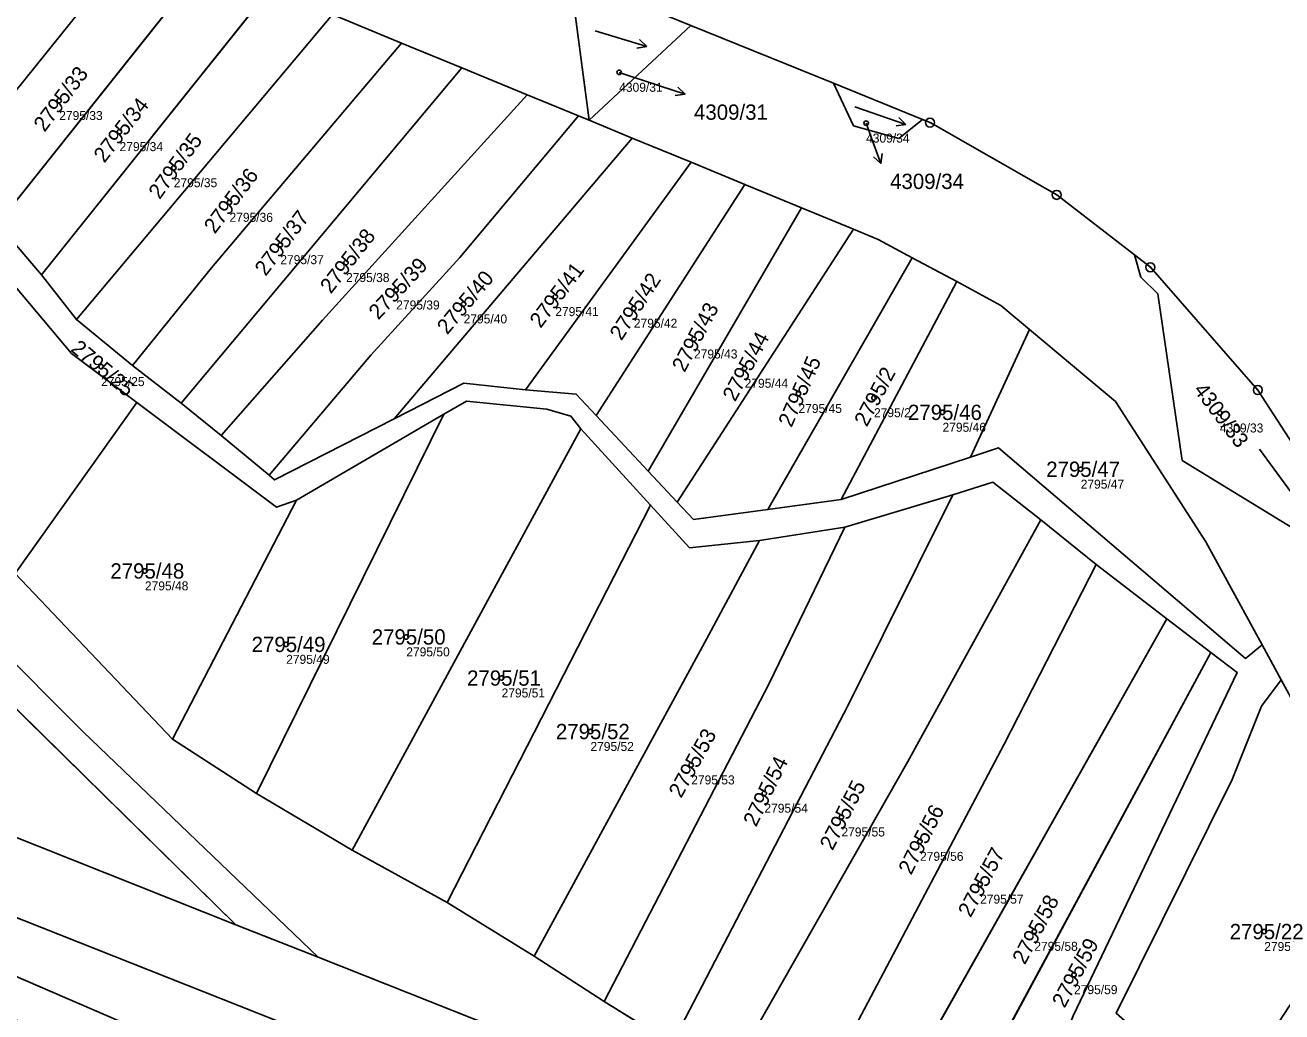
# Model space of a CAD drawing. Extents: x -739214 to -733252, y -1147612 to -1142842.
# Drawn here: x -737498.6 to -737358.8, y -1144401.4 to -1144291.6 of the extents above; entities that cross this region are included whole.
import ezdxf

# ---------------------------------------------------------------- set-up
doc = ezdxf.new("R2010")
doc.units = 0
for name, color, linetype in [('Definiční body', 7, 'Continuous'), ('Hranice parcel', 7, 'Continuous'), ('Parcelní čísla', 7, 'Continuous'), ('Polygon ku', 7, 'Continuous'), ('Polygon parcely', 7, 'Continuous'), ('Pop  PČ popisy', 7, 'Continuous'), ('Značky bodu BP', 7, 'Continuous'), ('Značky kultur', 7, 'Continuous')]:
    doc.layers.add(name, color=color, linetype=linetype)

msp = doc.modelspace()

# ---------------------------------------------------------------- linework, layer by layer
at = {"layer": 'Definiční body'}
for centre in [(-737432.55, -1144296.9), (-737494.83, -1144300.04), (-737405.09, -1144302.55), (-737488.12, -1144303.5), (-737482.09, -1144307.51), (-737475.89, -1144311.36), (-737470.24, -1144316.07), (-737462.93, -1144318.06), (-737457.35, -1144321.11), (-737439.66, -1144321.85), (-737449.85, -1144322.66), (-737430.92, -1144323.14), (-737424.23, -1144326.56), (-737490.17, -1144329.63), (-737418.6, -1144329.82), (-737412.61, -1144332.62), (-737404.21, -1144333.09), (-737396.59, -1144334.71), (-737365.74, -1144334.79), (-737381.22, -1144341.04), (-737485.3, -1144352.35), (-737456.23, -1144359.69), (-737469.59, -1144360.52), (-737445.63, -1144364.26), (-737435.75, -1144370.21), (-737424.54, -1144373.93), (-737416.4, -1144377.08), (-737407.83, -1144379.72), (-737399.09, -1144382.43), (-737392.41, -1144387.19), (-737386.38, -1144392.44), (-737360.81, -1144392.46), (-737381.96, -1144397.26)]:
    msp.add_circle(centre, 0.25, dxfattribs=at)
at = {"layer": 'Hranice parcel'}
for p, q in [((-737502.07, -1144314.24), (-737478.52, -1144284.68)), ((-737582.77, -1144286.02), (-737475.17, -1144391.69)), ((-737438.01, -1144286.21), (-737435.9, -1144302.23)), ((-737424.58, -1144291.67), (-737438.01, -1144286.21)), ((-737496.81, -1144319.43), (-737471.37, -1144287.62)), ((-737492.92, -1144324.38), (-737464.42, -1144290.48)), ((-737456.75, -1144293.64), (-737464.42, -1144290.48)), ((-737435.9, -1144302.23), (-737424.58, -1144291.67)), ((-737408.73, -1144298.11), (-737424.58, -1144291.67)), ((-737450.05, -1144296.4), (-737456.75, -1144293.64)), ((-737481.25, -1144333.69), (-737450.05, -1144296.4)), ((-737442.78, -1144299.39), (-737450.05, -1144296.4)), ((-737398.82, -1144302.14), (-737408.73, -1144298.11)), ((-737437.08, -1144301.74), (-737442.78, -1144299.39)), ((-737435.9, -1144302.23), (-737437.08, -1144301.74)), ((-737431.11, -1144304.2), (-737435.9, -1144302.23)), ((-737397.98, -1144302.48), (-737398.82, -1144302.14)), ((-737383.89, -1144310.52), (-737397.98, -1144302.48)), ((-737457.59, -1144335.43), (-737431.11, -1144304.2)), ((-737424.55, -1144306.9), (-737431.11, -1144304.2)), ((-737442.97, -1144332.19), (-737424.55, -1144306.9)), ((-737418.57, -1144309.37), (-737424.55, -1144306.9)), ((-737435.11, -1144335.05), (-737418.57, -1144309.37)), ((-737412.29, -1144311.95), (-737418.57, -1144309.37)), ((-737375.25, -1144317.2), (-737383.89, -1144310.52)), ((-737429.32, -1144341.24), (-737412.29, -1144311.95)), ((-737406.48, -1144314.34), (-737412.29, -1144311.95)), ((-737426.1, -1144344.69), (-737406.48, -1144314.34)), ((-737399.97, -1144317.54), (-737416, -1144345.53)), ((-737394.99, -1144320.15), (-737399.97, -1144317.54)), ((-737373.47, -1144318.58), (-737375.25, -1144317.2)), ((-737492.92, -1144324.38), (-737496.81, -1144319.43)), ((-737407.88, -1144344.42), (-737394.99, -1144320.15)), ((-737486.67, -1144329.49), (-737492.92, -1144324.38)), ((-737393.49, -1144339.68), (-737386.93, -1144325.49)), ((-737481.25, -1144333.69), (-737486.67, -1144329.49)), ((-737499.72, -1144352.62), (-737486.18, -1144333.6)), ((-737476.83, -1144337.27), (-737481.25, -1144333.69)), ((-737472.9, -1144377.11), (-737452.04, -1144334.92)), ((-737468.45, -1144344.48), (-737452.04, -1144334.92)), ((-737429.32, -1144341.24), (-737435.11, -1144335.05)), ((-737471.49, -1144341.7), (-737476.83, -1144337.27)), ((-737462.26, -1144383.41), (-737436.81, -1144336.54)), ((-737436.81, -1144336.54), (-737429.06, -1144345.03)), ((-737393.49, -1144339.68), (-737407.88, -1144344.42)), ((-737426.1, -1144344.69), (-737429.32, -1144341.24)), ((-737407.46, -1144347.49), (-737395.43, -1144343.89)), ((-737482.25, -1144371.07), (-737468.45, -1144344.48)), ((-737451.67, -1144389.22), (-737429.06, -1144345.03)), ((-737416, -1144345.53), (-737407.88, -1144344.42)), ((-737385.64, -1144346.65), (-737379.51, -1144351.64)), ((-737416.94, -1144348.97), (-737407.46, -1144347.49)), ((-737482.25, -1144371.07), (-737499.72, -1144352.62)), ((-737379.51, -1144351.64), (-737371.64, -1144357.66)), ((-737405.79, -1144418.29), (-737371.64, -1144357.66)), ((-737371.64, -1144357.66), (-737366.74, -1144361.41)), ((-737358.92, -1144364.45), (-737361.05, -1144360.55)), ((-737399.28, -1144421.75), (-737366.74, -1144361.41)), ((-737472.9, -1144377.11), (-737482.25, -1144371.07)), ((-737462.26, -1144383.41), (-737472.9, -1144377.11)), ((-737451.67, -1144389.22), (-737462.26, -1144383.41)), ((-737442.02, -1144395.2), (-737451.67, -1144389.22)), ((-737466.04, -1144395.32), (-737475.17, -1144391.69)), ((-737434.22, -1144400.22), (-737442.02, -1144395.2)), ((-737426.67, -1144404.91), (-737434.22, -1144400.22))]:
    msp.add_line(p, q, dxfattribs=at)
for points in [[(-737509.32, -1144310.65), (-737501.23, -1144300.88), (-737485.8, -1144281.68)], [(-737466.04, -1144395.32), (-737492.16, -1144370.24), (-737532.88, -1144329.44), (-737578.49, -1144285.03)], [(-737486.67, -1144329.49), (-737477.89, -1144318.64), (-737456.75, -1144293.64)], [(-737408.73, -1144298.11), (-737406.48, -1144302.83), (-737401.44, -1144304.26), (-737398.82, -1144302.14)], [(-737476.83, -1144337.27), (-737465.54, -1144324.44), (-737442.78, -1144299.39)], [(-737471.49, -1144341.7), (-737460.19, -1144328.34), (-737450.27, -1144317.49), (-737437.08, -1144301.74)], [(-737486.18, -1144333.6), (-737493.46, -1144328.15), (-737503.44, -1144316.34), (-737530.27, -1144302.72)], [(-737496.81, -1144319.43), (-737500.24, -1144315.38), (-737502.07, -1144314.24)], [(-737399.97, -1144317.54), (-737403.75, -1144315.47), (-737406.48, -1144314.34)], [(-737375.25, -1144317.2), (-737374.53, -1144319.66), (-737372.66, -1144321.53), (-737369.92, -1144340.05), (-737349.14, -1144352.77)], [(-737352.83, -1144345.62), (-737361.52, -1144332.23), (-737373.47, -1144318.58)], [(-737386.93, -1144325.49), (-737390.12, -1144322.82), (-737394.99, -1144320.15)], [(-737361.05, -1144360.55), (-737367.3, -1144349.12), (-737377.34, -1144333.52), (-737386.93, -1144325.49)], [(-737442.97, -1144332.19), (-737449.83, -1144331.46), (-737457.59, -1144335.43)], [(-737435.11, -1144335.05), (-737437.33, -1144332.67), (-737442.97, -1144332.19)], [(-737486.18, -1144333.6), (-737470.65, -1144345.24), (-737468.45, -1144344.48)], [(-737452.04, -1144334.92), (-737449.52, -1144333.45), (-737440.59, -1144334.36), (-737437.92, -1144335.13), (-737436.81, -1144336.54)], [(-737457.59, -1144335.43), (-737470.9, -1144342.23), (-737471.49, -1144341.7)], [(-737361.05, -1144360.55), (-737362.91, -1144362.08), (-737390.38, -1144338.66), (-737393.49, -1144339.68)], [(-737395.43, -1144343.89), (-737390.99, -1144342.49), (-737385.64, -1144346.65)], [(-737426.67, -1144404.91), (-737407.08, -1144367.27), (-737395.43, -1144343.89)], [(-737429.06, -1144345.03), (-737424.74, -1144349.77), (-737416.94, -1144348.97)], [(-737416, -1144345.53), (-737424.28, -1144346.64), (-737426.1, -1144344.69)], [(-737420.59, -1144408.93), (-737400.46, -1144373.56), (-737385.64, -1144346.65)], [(-737434.22, -1144400.22), (-737415.88, -1144364.85), (-737407.46, -1144347.49)], [(-737442.02, -1144395.2), (-737422.83, -1144359.93), (-737416.94, -1144348.97)], [(-737475.17, -1144391.69), (-737515.39, -1144375.72), (-737589.81, -1144352.43)], [(-737412.32, -1144414.39), (-737389.73, -1144371.61), (-737379.51, -1144351.64)], [(-737366.74, -1144361.41), (-737363.81, -1144363.65), (-737382.06, -1144401.83)], [(-737358.92, -1144364.45), (-737361.1, -1144367.39), (-737364.36, -1144375.55), (-737377.29, -1144401.55), (-737365.37, -1144412.02)], [(-737348, -1144385.38), (-737353.69, -1144374.01), (-737358.92, -1144364.45)], [(-737440.41, -1144423.04), (-737518.02, -1144389.53), (-737570.21, -1144367.47)], [(-737570.21, -1144367.47), (-737546.96, -1144375.73), (-737518.83, -1144383.3), (-737458.74, -1144407.1)], [(-737394.5, -1144435.43), (-737406.91, -1144422.57), (-737423.56, -1144412.19), (-737466.04, -1144395.32)]]:
    msp.add_lwpolyline(points, dxfattribs=at)
at = {"layer": 'Polygon ku'}
msp.add_lwpolyline([(-737309.06, -1144253.23), (-737338.64, -1144329.35), (-737348.64, -1144340.82), (-737352.83, -1144345.62), (-737361.52, -1144332.23), (-737373.47, -1144318.58), (-737375.25, -1144317.2), (-737383.89, -1144310.52), (-737397.98, -1144302.48), (-737398.82, -1144302.14), (-737408.73, -1144298.11), (-737424.58, -1144291.67), (-737438.01, -1144286.21), (-737467.45, -1144274.25), (-737487.38, -1144266.16), (-737491.23, -1144264.59), (-737500.02, -1144259.67)], dxfattribs=at)
at = {"layer": 'Polygon parcely'}
for points in [[(-737499.7, -1144275.41), (-737497.9, -1144276.69), (-737492.56, -1144278.89), (-737485.8, -1144281.68), (-737478.52, -1144284.68), (-737471.37, -1144287.62), (-737464.42, -1144290.48), (-737456.75, -1144293.64), (-737450.05, -1144296.4), (-737442.78, -1144299.39), (-737437.08, -1144301.74), (-737435.9, -1144302.23), (-737438.01, -1144286.21), (-737467.45, -1144274.25), (-737470.28, -1144275.15), (-737481.75, -1144275), (-737487.38, -1144266.16), (-737491.23, -1144264.59), (-737500.02, -1144259.67)], [(-737349.14, -1144352.77), (-737369.92, -1144340.05), (-737372.66, -1144321.53), (-737374.53, -1144319.66), (-737375.25, -1144317.2), (-737383.89, -1144310.52), (-737397.98, -1144302.48), (-737398.82, -1144302.14), (-737401.44, -1144304.26), (-737406.48, -1144302.83), (-737408.73, -1144298.11), (-737424.58, -1144291.67), (-737435.9, -1144302.23), (-737431.11, -1144304.2), (-737424.55, -1144306.9), (-737418.57, -1144309.37), (-737412.29, -1144311.95), (-737406.48, -1144314.34), (-737403.75, -1144315.47), (-737399.97, -1144317.54), (-737394.99, -1144320.15), (-737390.12, -1144322.82), (-737386.93, -1144325.49), (-737377.34, -1144333.52), (-737367.3, -1144349.12), (-737361.05, -1144360.55), (-737358.92, -1144364.45), (-737353.69, -1144374.01)], [(-737503.44, -1144316.34), (-737493.46, -1144328.15), (-737486.18, -1144333.6), (-737470.65, -1144345.24), (-737468.45, -1144344.48), (-737452.04, -1144334.92), (-737449.52, -1144333.45), (-737440.59, -1144334.36), (-737437.92, -1144335.13), (-737436.81, -1144336.54), (-737429.06, -1144345.03), (-737424.74, -1144349.77), (-737416.94, -1144348.97), (-737407.46, -1144347.49), (-737395.43, -1144343.89), (-737390.99, -1144342.49), (-737385.64, -1144346.65), (-737379.51, -1144351.64), (-737371.64, -1144357.66), (-737366.74, -1144361.41), (-737363.81, -1144363.65), (-737382.06, -1144401.83)], [(-737377.29, -1144401.55), (-737364.36, -1144375.55), (-737361.1, -1144367.39), (-737358.92, -1144364.45), (-737361.05, -1144360.55), (-737362.91, -1144362.08), (-737390.38, -1144338.66), (-737393.49, -1144339.68), (-737407.88, -1144344.42), (-737416, -1144345.53), (-737424.28, -1144346.64), (-737426.1, -1144344.69), (-737429.32, -1144341.24), (-737435.11, -1144335.05), (-737437.33, -1144332.67), (-737442.97, -1144332.19), (-737449.83, -1144331.46), (-737457.59, -1144335.43), (-737470.9, -1144342.23), (-737471.49, -1144341.7), (-737476.83, -1144337.27), (-737481.25, -1144333.69), (-737486.67, -1144329.49), (-737492.92, -1144324.38), (-737496.81, -1144319.43), (-737500.24, -1144315.38)], [(-737532.88, -1144329.44), (-737492.16, -1144370.24), (-737466.04, -1144395.32), (-737423.56, -1144412.19), (-737406.91, -1144422.57), (-737394.5, -1144435.43), (-737391.3, -1144426.57), (-737399.28, -1144421.75), (-737405.79, -1144418.29), (-737412.32, -1144414.39), (-737420.59, -1144408.93), (-737426.67, -1144404.91), (-737434.22, -1144400.22), (-737442.02, -1144395.2), (-737451.67, -1144389.22), (-737462.26, -1144383.41), (-737472.9, -1144377.11), (-737482.25, -1144371.07), (-737499.72, -1144352.62)], [(-737518.83, -1144383.3), (-737458.74, -1144407.1), (-737448.94, -1144410.98), (-737427.83, -1144419.35), (-737411.92, -1144429.07), (-737399.1, -1144440.34), (-737385.11, -1144452.65), (-737378.93, -1144463.01), (-737374.74, -1144470.47), (-737373.83, -1144469.89), (-737370.42, -1144467.71), (-737369.54, -1144467.14), (-737368.51, -1144468.16), (-737373.19, -1144460.16), (-737378.34, -1144453.15), (-737381.35, -1144449.05), (-737391.03, -1144439.02), (-737394.5, -1144435.43), (-737406.91, -1144422.57), (-737423.56, -1144412.19), (-737466.04, -1144395.32), (-737475.17, -1144391.69), (-737515.39, -1144375.72)]]:
    msp.add_lwpolyline(points, dxfattribs=at)
for points in [[(-737485.8, -1144281.68), (-737492.56, -1144278.89), (-737515.43, -1144307.53), (-737509.32, -1144310.65), (-737501.23, -1144300.88)], [(-737475.17, -1144391.69), (-737466.04, -1144395.32), (-737492.16, -1144370.24), (-737532.88, -1144329.44), (-737578.49, -1144285.03), (-737582.59, -1144281.04), (-737582.47, -1144284.34), (-737582.77, -1144286.02)], [(-737478.52, -1144284.68), (-737485.8, -1144281.68), (-737501.23, -1144300.88), (-737509.32, -1144310.65), (-737502.07, -1144314.24)], [(-737471.37, -1144287.62), (-737478.52, -1144284.68), (-737502.07, -1144314.24), (-737500.24, -1144315.38), (-737496.81, -1144319.43)], [(-737589.81, -1144352.43), (-737515.39, -1144375.72), (-737475.17, -1144391.69), (-737582.77, -1144286.02), (-737593.84, -1144347.91)], [(-737438.01, -1144286.21), (-737435.9, -1144302.23), (-737424.58, -1144291.67)], [(-737464.42, -1144290.48), (-737471.37, -1144287.62), (-737496.81, -1144319.43), (-737492.92, -1144324.38)], [(-737477.89, -1144318.64), (-737456.75, -1144293.64), (-737464.42, -1144290.48), (-737492.92, -1144324.38), (-737486.67, -1144329.49)], [(-737450.05, -1144296.4), (-737456.75, -1144293.64), (-737477.89, -1144318.64), (-737486.67, -1144329.49), (-737481.25, -1144333.69)], [(-737442.78, -1144299.39), (-737450.05, -1144296.4), (-737481.25, -1144333.69), (-737476.83, -1144337.27), (-737465.54, -1144324.44)], [(-737408.73, -1144298.11), (-737406.48, -1144302.83), (-737401.44, -1144304.26), (-737398.82, -1144302.14)], [(-737460.19, -1144328.34), (-737450.27, -1144317.49), (-737437.08, -1144301.74), (-737442.78, -1144299.39), (-737465.54, -1144324.44), (-737476.83, -1144337.27), (-737471.49, -1144341.7)], [(-737435.9, -1144302.23), (-737437.08, -1144301.74), (-737450.27, -1144317.49), (-737460.19, -1144328.34), (-737471.49, -1144341.7), (-737470.9, -1144342.23), (-737457.59, -1144335.43), (-737431.11, -1144304.2)], [(-737518.03, -1144325.29), (-737499.72, -1144352.62), (-737486.18, -1144333.6), (-737493.46, -1144328.15), (-737503.44, -1144316.34), (-737530.27, -1144302.72), (-737534.41, -1144308.3)], [(-737442.97, -1144332.19), (-737424.55, -1144306.9), (-737431.11, -1144304.2), (-737457.59, -1144335.43), (-737449.83, -1144331.46)], [(-737418.57, -1144309.37), (-737424.55, -1144306.9), (-737442.97, -1144332.19), (-737437.33, -1144332.67), (-737435.11, -1144335.05)], [(-737412.29, -1144311.95), (-737418.57, -1144309.37), (-737435.11, -1144335.05), (-737429.32, -1144341.24)], [(-737426.1, -1144344.69), (-737406.48, -1144314.34), (-737412.29, -1144311.95), (-737429.32, -1144341.24)], [(-737403.75, -1144315.47), (-737406.48, -1144314.34), (-737426.1, -1144344.69), (-737424.28, -1144346.64), (-737416, -1144345.53), (-737399.97, -1144317.54)], [(-737407.88, -1144344.42), (-737394.99, -1144320.15), (-737399.97, -1144317.54), (-737416, -1144345.53)], [(-737361.52, -1144332.23), (-737373.47, -1144318.58), (-737375.25, -1144317.2), (-737374.53, -1144319.66), (-737372.66, -1144321.53), (-737369.92, -1144340.05), (-737349.14, -1144352.77), (-737352.83, -1144345.62)], [(-737393.49, -1144339.68), (-737386.93, -1144325.49), (-737390.12, -1144322.82), (-737394.99, -1144320.15), (-737407.88, -1144344.42)], [(-737361.05, -1144360.55), (-737367.3, -1144349.12), (-737377.34, -1144333.52), (-737386.93, -1144325.49), (-737393.49, -1144339.68), (-737390.38, -1144338.66), (-737362.91, -1144362.08)], [(-737468.45, -1144344.48), (-737470.65, -1144345.24), (-737486.18, -1144333.6), (-737499.72, -1144352.62), (-737482.25, -1144371.07)], [(-737436.81, -1144336.54), (-737437.92, -1144335.13), (-737440.59, -1144334.36), (-737449.52, -1144333.45), (-737452.04, -1144334.92), (-737472.9, -1144377.11), (-737462.26, -1144383.41)], [(-737570.21, -1144367.47), (-737605.92, -1144354.78), (-737662.13, -1144335.64), (-737606.49, -1144357.15), (-737594.07, -1144362.65), (-737564.44, -1144374.81), (-737504.72, -1144400.14), (-737395.05, -1144446.72), (-737378.93, -1144463.01), (-737385.11, -1144452.65), (-737399.1, -1144440.34), (-737431.49, -1144426.79), (-737440.41, -1144423.04), (-737518.02, -1144389.53)], [(-737452.04, -1144334.92), (-737468.45, -1144344.48), (-737482.25, -1144371.07), (-737472.9, -1144377.11)], [(-737451.67, -1144389.22), (-737429.06, -1144345.03), (-737436.81, -1144336.54), (-737462.26, -1144383.41)], [(-737400.46, -1144373.56), (-737385.64, -1144346.65), (-737390.99, -1144342.49), (-737395.43, -1144343.89), (-737407.08, -1144367.27), (-737426.67, -1144404.91), (-737420.59, -1144408.93)], [(-737407.08, -1144367.27), (-737395.43, -1144343.89), (-737407.46, -1144347.49), (-737415.88, -1144364.85), (-737434.22, -1144400.22), (-737426.67, -1144404.91)], [(-737442.02, -1144395.2), (-737422.83, -1144359.93), (-737416.94, -1144348.97), (-737424.74, -1144349.77), (-737429.06, -1144345.03), (-737451.67, -1144389.22)], [(-737412.32, -1144414.39), (-737389.73, -1144371.61), (-737379.51, -1144351.64), (-737385.64, -1144346.65), (-737400.46, -1144373.56), (-737420.59, -1144408.93)], [(-737415.88, -1144364.85), (-737407.46, -1144347.49), (-737416.94, -1144348.97), (-737422.83, -1144359.93), (-737442.02, -1144395.2), (-737434.22, -1144400.22)], [(-737405.79, -1144418.29), (-737371.64, -1144357.66), (-737379.51, -1144351.64), (-737389.73, -1144371.61), (-737412.32, -1144414.39)], [(-737399.28, -1144421.75), (-737366.74, -1144361.41), (-737371.64, -1144357.66), (-737405.79, -1144418.29)], [(-737391.3, -1144426.57), (-737387.79, -1144416.02), (-737382.06, -1144401.83), (-737363.81, -1144363.65), (-737366.74, -1144361.41), (-737399.28, -1144421.75)], [(-737365.37, -1144412.02), (-737348, -1144385.38), (-737353.69, -1144374.01), (-737358.92, -1144364.45), (-737361.1, -1144367.39), (-737364.36, -1144375.55), (-737377.29, -1144401.55)], [(-737458.74, -1144407.1), (-737518.83, -1144383.3), (-737546.96, -1144375.73), (-737570.21, -1144367.47), (-737518.02, -1144389.53), (-737440.41, -1144423.04)]]:
    msp.add_lwpolyline(points, close=True, dxfattribs=at)
at = {"layer": 'Pop  PČ popisy'}
for p, q in [((-737432.55, -1144296.9), (-737428.08, -1144298.39)), ((-737428.08, -1144298.39), (-737425.23, -1144299.32)), ((-737425.23, -1144299.32), (-737426.33, -1144299.48)), ((-737425.23, -1144299.32), (-737426.02, -1144298.53)), ((-737405.09, -1144302.55), (-737404.47, -1144304.23)), ((-737404.47, -1144304.23), (-737403.44, -1144307.05)), ((-737403.44, -1144307.05), (-737404.26, -1144306.28)), ((-737403.44, -1144307.05), (-737403.32, -1144305.94))]:
    msp.add_line(p, q, dxfattribs=at)
at = {"layer": 'Značky bodu BP'}
for centre, radius in [((-737397.98, -1144302.48), 0.5), ((-737397.98, -1144302.48), 0.0303), ((-737383.89, -1144310.52), 0.5), ((-737383.89, -1144310.52), 0.0303), ((-737373.47, -1144318.58), 0.5), ((-737373.47, -1144318.58), 0.0303), ((-737361.52, -1144332.23), 0.5), ((-737361.52, -1144332.23), 0.0303)]:
    msp.add_circle(centre, radius, dxfattribs=at)
at = {"layer": 'Značky kultur'}
for p, q in [((-737435.22, -1144292.27), (-737429.49, -1144294.02)), ((-737429.49, -1144294.02), (-737430.28, -1144293.26)), ((-737429.49, -1144294.02), (-737430.57, -1144294.21)), ((-737406.34, -1144300.74), (-737400.67, -1144302.69)), ((-737400.67, -1144302.69), (-737401.43, -1144301.9)), ((-737400.67, -1144302.69), (-737401.76, -1144302.85)), ((-737361.32, -1144338.81), (-737357.79, -1144343.67))]:
    msp.add_line(p, q, dxfattribs=at)

# ---------------------------------------------------------------- texts
at = {"layer": 'Definiční body'}
for s, p in [('4309/31', (-737432.55, -1144299.06)), ('2795/33', (-737494.83, -1144302.2)), ('4309/34', (-737405.09, -1144304.71)), ('2795/34', (-737488.12, -1144305.66)), ('2795/35', (-737482.09, -1144309.67)), ('2795/36', (-737475.89, -1144313.52)), ('2795/37', (-737470.24, -1144318.23)), ('2795/38', (-737462.93, -1144320.22)), ('2795/39', (-737457.35, -1144323.27)), ('2795/41', (-737439.66, -1144324.01)), ('2795/40', (-737449.85, -1144324.82)), ('2795/42', (-737430.92, -1144325.3)), ('2795/43', (-737424.23, -1144328.72)), ('2795/25', (-737490.17, -1144331.79)), ('2795/44', (-737418.6, -1144331.98)), ('2795/45', (-737412.61, -1144334.78)), ('2795/2', (-737404.21, -1144335.25)), ('2795/46', (-737396.59, -1144336.87)), ('4309/33', (-737365.74, -1144336.95)), ('2795/47', (-737381.22, -1144343.2)), ('2795/48', (-737485.3, -1144354.51)), ('2795/50', (-737456.23, -1144361.85)), ('2795/49', (-737469.59, -1144362.68)), ('2795/51', (-737445.63, -1144366.42)), ('2795/52', (-737435.75, -1144372.37)), ('2795/53', (-737424.54, -1144376.09)), ('2795/54', (-737416.4, -1144379.24)), ('2795/55', (-737407.83, -1144381.88)), ('2795/56', (-737399.09, -1144384.59)), ('2795/57', (-737392.41, -1144389.35)), ('2795/58', (-737386.38, -1144394.6)), ('2795/22', (-737360.81, -1144394.62)), ('2795/59', (-737381.96, -1144399.42))]:
    msp.add_text(s, height=1, dxfattribs=at).set_placement(p)
at = {"layer": 'Parcelní čísla'}
for s, rotation, p in [('2795/33', 53, (-737496.46, -1144303.62)), ('2795/34', 52, (-737489.81, -1144307.05)), ('2795/35', 54, (-737483.66, -1144311.11)), ('2795/36', 53, (-737477.52, -1144314.94)), ('2795/37', 53, (-737471.87, -1144319.65)), ('2795/38', 52, (-737464.62, -1144321.61)), ('2795/39', 47, (-737459.34, -1144324.5)), ('2795/40', 50, (-737451.67, -1144326.15)), ('2795/41', 53, (-737441.29, -1144325.43)), ('2795/42', 57, (-737432.3, -1144326.82)), ('2795/43', 62, (-737425.28, -1144330.35)), ('2795/44', 62, (-737419.65, -1144333.61)), ('2795/25', 320, (-737493.66, -1144327.81)), ('2795/45', 66, (-737413.39, -1144336.47)), ('2795/2', 62, (-737405.01, -1144336.41)), ('4309/33', 307, (-737368.73, -1144332.24)), ('2795/53', 61, (-737425.66, -1144377.7)), ('2795/54', 64, (-737417.32, -1144380.9)), ('2795/55', 63, (-737408.82, -1144383.53)), ('2795/56', 63, (-737400.08, -1144386.24)), ('2795/57', 62, (-737393.46, -1144390.98)), ('2795/58', 62, (-737387.43, -1144396.23)), ('2795/59', 62, (-737383.01, -1144401.05))]:
    msp.add_text(s, height=1.7, rotation=rotation, dxfattribs=at).set_placement(p)
for s, p in [('4309/31', (-737424.23, -1144302.17)), ('4309/34', (-737402.42, -1144309.87)), ('2795/46', (-737400.43, -1144335.56)), ('2795/47', (-737385.06, -1144341.89)), ('2795/48', (-737489.14, -1144353.2)), ('2795/49', (-737473.43, -1144361.37)), ('2795/50', (-737460.07, -1144360.54)), ('2795/51', (-737449.47, -1144365.11)), ('2795/52', (-737439.59, -1144371.06)), ('2795/22', (-737364.65, -1144393.31))]:
    msp.add_text(s, height=1.7, dxfattribs=at).set_placement(p)

doc.saveas('drawing.dxf')
